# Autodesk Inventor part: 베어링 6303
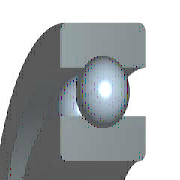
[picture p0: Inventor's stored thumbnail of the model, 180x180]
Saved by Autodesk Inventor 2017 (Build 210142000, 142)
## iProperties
IsCustomPart: 1
Created: 2012-02
Part Number: 베어링 6303
Material: 강철, 연강
Description: 단열 볼 베어링
Document SubType Name: Modeling
Standard: JIS B 1521
Designer: mdu-01
Standards Organization: JIS
Language: ko-KR
Size Designation: SKF 6303
Categories: <MemberInstance><Categories><Category DisplayName="샤프트 부품" InternalName="7f7aeb1f-a693-4053-b835-cee3144e0d98" Mnemonic="SHFT"><Category DisplayName="베어링" Inter
Density: 7.86 g/cm^3
Mass: 109.196 g
Surface Area: 91.3613 cm^2
Volume: 13.8926 cm^3
Appearance: 노란색
Author: mdu-01
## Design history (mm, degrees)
node "WorkPoint1"
node "WorkAxis1"
node "WorkPlane3"
node "WorkPlane4"
node "WorkPoint2"
body "Solid1"
node "스케치1"
revolve "회전1" stored, may be unused: angle "d6" = 360 deg
revolve "회전2" stored, may be unused: angle "d10" = 360 deg
node "스케치4"
revolve "회전3" stored, may be unused: angle "d16" = 360 deg
pattern_circular "원형 배열1" dims "d17" = 57.33333 (= msp_pocet), angle "d19" = 360 deg
fillet "모깎기1" dims "d20" = 1 (= r)
sketch "스케치2"
  geometry: L1 (8.5, 14)-(23.5, 14); L2 (8.5, 0)-(8.5, 14); L3 (23.5, 0)-(8.5, 0); L4 (23.5, 14)-(23.5, 0); L5 (0, 0)-(0, 20); L6 (0, 0)-(0, 20); L7 (-7.2, 0)-(43.2, 0) reference
  constraints: 12 end point, 3 vertical, 2 horizontal, 1 collinear, 1 other
  dimensions: "d1" = 17 diameter of L1.start L5 (= Diam); "d3" = 47 diameter of L1.end L5 (= DD); "d5" = 14 distance of L2.start L1.start (= msp_mdtd2)
sketch "스케치3"
  geometry: L1 (18.7, 14)-(18.7, 10.6); L2 (13.3, 14)-(18.7, 14); L3 (13.3, 10.6)-(13.3, 14); L4 (13.3, 0)-(13.3, 3.4); L5 (18.7, 0)-(13.3, 0); L6 (18.7, 3.4)-(18.7, 0); L7 (23.5, 0)-(-23.5, 0) reference; L8 (23.5, 14)-(-23.5, 14) reference; L9 (0, -42.29)-(0, 61.29); L10 (0, 82.007)-(0, -63.007) reference; A1 r 4.5 centre (16, 7) between (18.7, 3.4) and (18.7, 10.6); A2 r 4.5 centre (16, 7) between (13.3, 10.6) and (13.3, 3.4)
  constraints: 14 end point, 4 collinear, 4 point on circle, 4 vertical, 2 centre point, 2 concentric, 2 horizontal, 2 point on line
  dimensions: "d9" = 9 diameter of A1 (= msp_mdtd6); "d21" = 13.3 distance between parallel lines of L9 L4 (= 0.5 x msp_d1); "d22" = 16 distance from line of L9 A1.centre (= 0.5 x msp_ds); "d23" = 18.7 distance between parallel lines of L9 L6 (= 0.5 x msp_dd1)
sketch "스케치5"
  geometry: L1 (16, 2.5)-(16, 11.5); L2 (18.7, 0)-(-18.7, 0) reference; L3 (16, 2.5)-(16, 11.5); A1 r 4.5 centre (16, 7) between (16, 2.5) and (16, 11.5); A2 r 4.5 centre (16, 7) between (18.7, 3.4) and (18.7, 10.6) reference
  constraints: 4 end point, 2 point on circle, 1 centre point, 1 concentric, 1 vertical
  dimensions: "d13" = 0 horizontal distance of A1.centre L1.start; "d15" = 9.0001 diameter of A1 (computed from msp_mdtd6)
other parameters: "Diam" = 17 [user parameter; used in 3 equation terms], "DD" = 47 [user parameter; used in 3 equation terms], "B" = 14 [user parameter; used in 1 equation term], "r" = 1 [user parameter; used in 1 equation term], "msp_ds" = 32 (= 0.5 x Diam + 0.5 x DD) [user parameter; used in 5 equation terms], "msp_d0" = 9 (= -0.3 x Diam + 0.3 x DD) [user parameter; used in 4 equation terms], "msp_d1" = 26.6 (= msp_ds - 0.6 x msp_d0) [user parameter; used in 1 equation term], "msp_dd1" = 37.4 (= msp_ds + 0.6 x msp_d0) [user parameter; used in 1 equation term], "msp_pom" = 48 (= 1.5 x msp_ds) [user parameter; used in 1 equation term], "msp_mdtd2" = 14 (= B) [user parameter; used in 3 equation terms], "msp_mdtd4" = 32 (= msp_ds) [user parameter], "msp_mdtd6" = 9 (= msp_d0) [user parameter; used in 2 equation terms], "msp_mdtd7" = 7 (= 0.5 x msp_mdtd2) [user parameter], "msp_pocet" = 57.33333 (computed from msp_d0, msp_pom) [user parameter; used in 1 equation term], "d2" = 72 (derived), "d4" = 19 (derived), "d7" = 0, "d8" = 15.6 (derived), "d11" = -14 (computed from msp_mdtd2), "d12" = 0 (derived), "d14" = 15.6001 (derived), "d26" = 0, "d27" = 0, "d28" = 0, "d29" = 0, "d30" = 0
